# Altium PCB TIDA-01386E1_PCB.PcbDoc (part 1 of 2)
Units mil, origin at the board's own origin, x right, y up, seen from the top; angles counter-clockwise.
Board outline 3000 x 700 mil, 4 copper layers (Top Layer, Signal Layer 1, Signal Layer 2, Bottom Layer), stack 90.316 mil thick; 67 components, 41 nets, 217 pads, 102 vias.
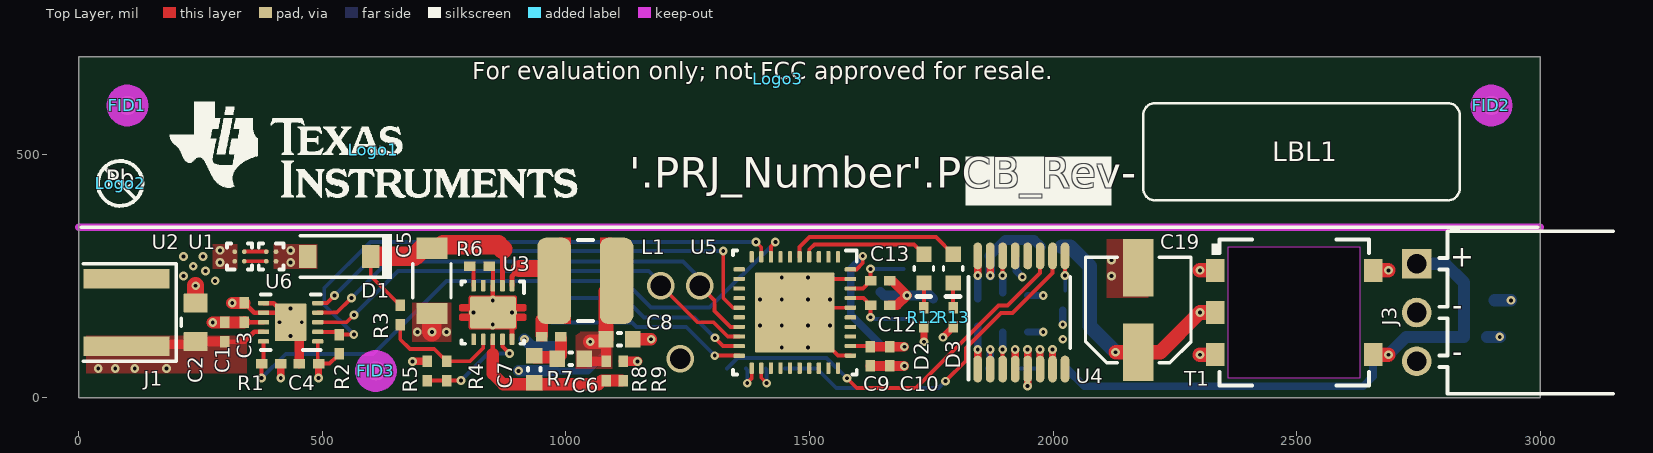
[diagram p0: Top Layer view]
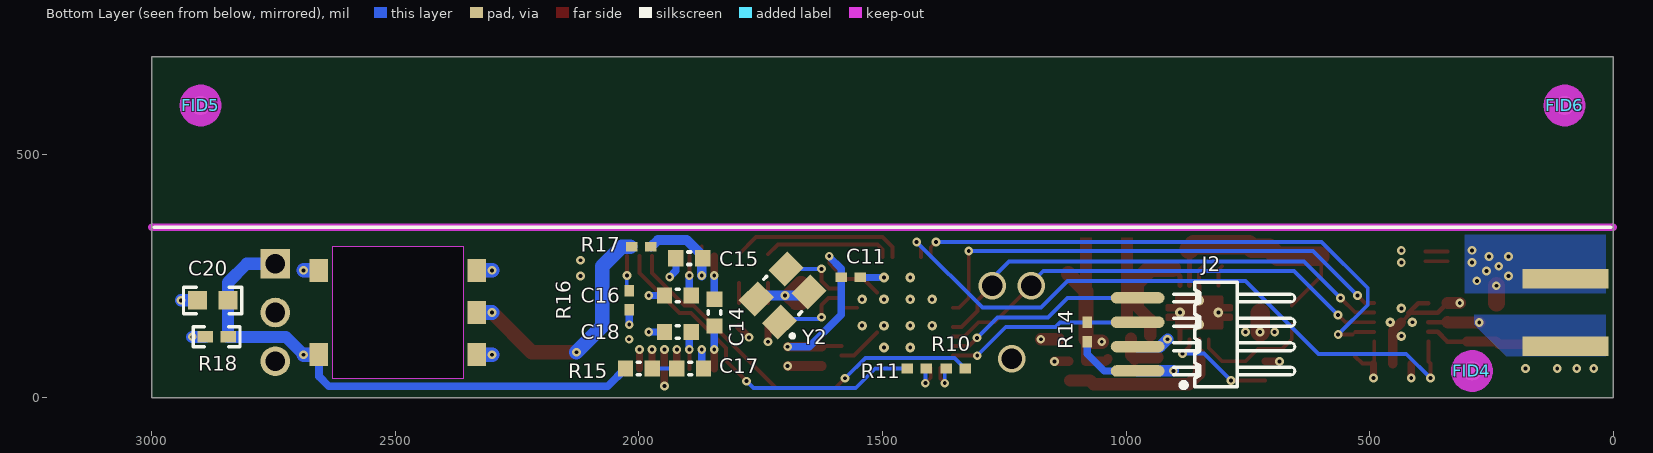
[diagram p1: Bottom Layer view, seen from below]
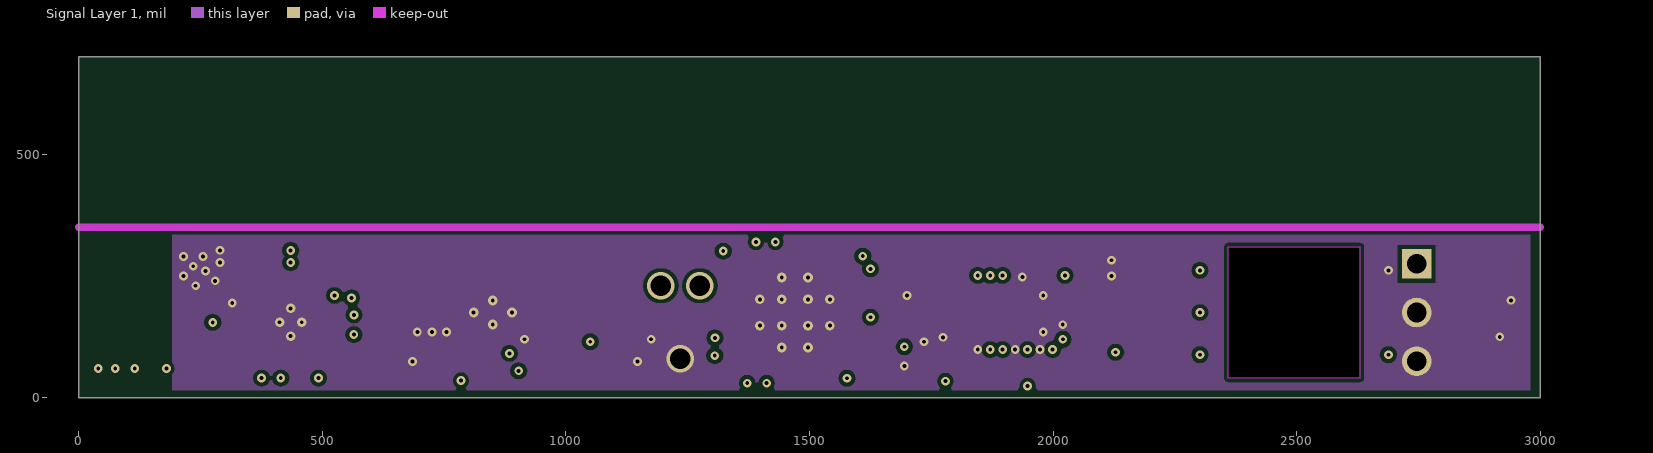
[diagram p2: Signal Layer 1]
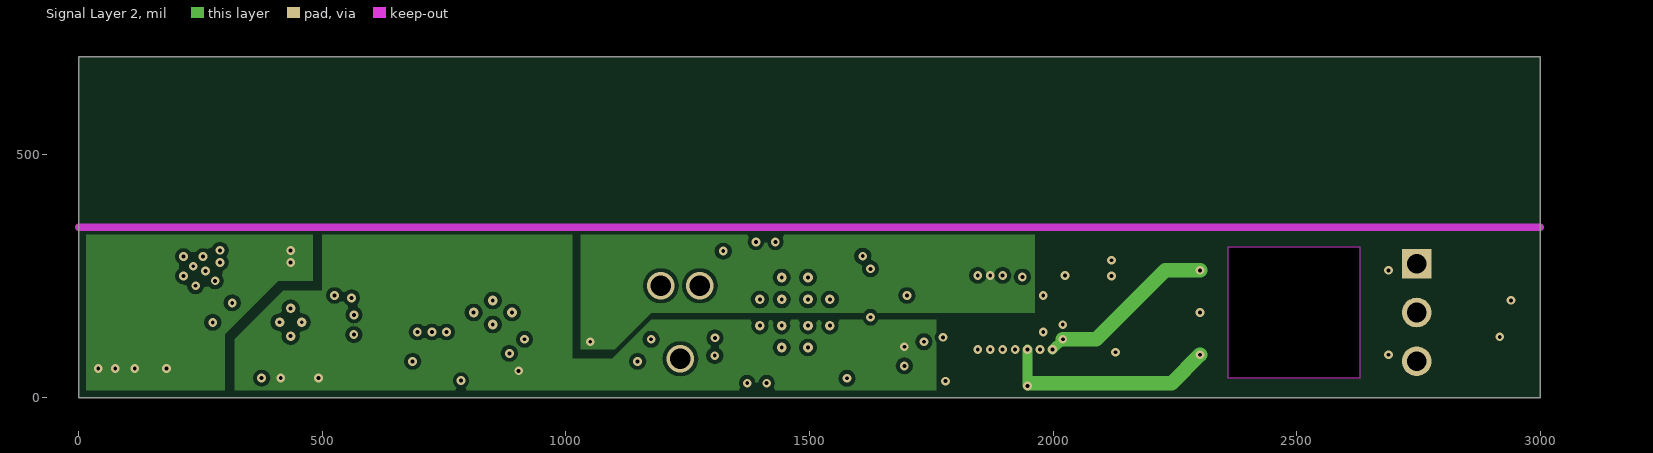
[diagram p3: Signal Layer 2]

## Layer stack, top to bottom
Top Solder: solder mask 0.4, Solder Resist, Dk 3.5
Top Layer: signal copper 1.457
Dielectric1: prepreg 20.079, FR-4, Dk 4.8
Signal Layer 1: signal copper 1.378
Dielectric 2: core 44.488, FR-4, Dk 4.8
Signal Layer 2: signal copper 1.378
Dielectric 3: prepreg 20.079, FR-4, Dk 4.8
Bottom Layer: signal copper 1.457
Bottom Solder: solder mask 0.4, Solder Resist, Dk 3.5

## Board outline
0,0 0,700 3000,700 3000,0
cut-out: 2630,40 2360,40 2360,310 2630,310

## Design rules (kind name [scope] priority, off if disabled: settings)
AcuteAngle [All] p1: minimum=4.50000000000000E+0001 checktracksonly=FALSE
AssemblyTestPointUsage [All] p1: valid=2
BoardOutlineClearance BoardOutlineClearance_MountingHoles [OnCopper and InComponentClass('Mounting Holes')] p1: gap=40
BoardOutlineClearance BoardOutlineClearance_Poly [OnCopper and IsPoly] p2: gap=20 except(15: Track-OutlineEdge Poly-OutlineEdge; 25: Text-OutlineEdge Text-CutoutEdge Text-CavityEdge Text-SplitBarrior Text-SplitContinuation)
BoardOutlineClearance [OnCopper and Not InComponentClass('Logo') and not InComponentClass('FiducialMark') and not InRegion(1000,500,4000,800) and not InPoly and not InComponent('J1')] p3: gap=75 except(7.87: Track-CutoutEdge SMDPad-CutoutEdge Fill-CutoutEdge Poly-CutoutEdge; 15: Track-OutlineEdge SMDPad-OutlineEdge Via-OutlineEdge Poly-OutlineEdge; 40: Arc-OutlineEdge Arc-CutoutEdge THPad-OutlineEdge THPad-CutoutEdge Via-CutoutEdge Fill-OutlineEdge Text-OutlineEdge Text-CutoutEdge)
Clearance Clearance_Keepouts [((IsTrack Or IsArc) And Not InPoly) And IsFree and IsKeepOut vs ((IsTrack Or IsArc) And Not InPoly) And IsFree and IsKeepOut] p1: gap=0
Clearance Clearance_Poly [InPolygon] p2: gap=25 except(8: Track-Poly SMDPad-Poly THPad-Poly Via-Poly Poly-Poly Poly-Region)
Clearance [All] p3: gap=7.87 except(6: Track-Track Track-SMDPad Track-THPad Track-Via; 7.5: Via-Via)
ComponentClearance ComponentClearance_MountingHoles_FiducialMarks [InComponentClass('Mounting Holes') vs InComponentClass('FiducialMark')] p1: gap=50 collisioncheckmode=3 verticalgap=10 showdistances=FALSE
ComponentClearance ComponentClearance_Shunt [InComponentClass('Header') vs InComponentClass('Shunt')] p2: gap=0 collisioncheckmode=3 verticalgap=0 showdistances=FALSE
ComponentClearance ComponentClearance_Logo [InComponentClass('Logo')] p3: gap=20 collisioncheckmode=3 verticalgap=10 showdistances=FALSE
ComponentClearance ComponentClearance_ScrewToNut [(HasFootprint('NY PMS 440 0025 PH')) vs (HasFootprint('Keystone_1902C'))] p4: gap=5 collisioncheckmode=3 verticalgap=10 showdistances=FALSE
ComponentClearance ComponentClearance_MountingHoles [InComponentClass('Mounting Holes')] p5: gap=250 collisioncheckmode=3 verticalgap=100000 showdistances=FALSE
ComponentClearance ComponentClearance_SmallPassives [HasFootprint('0201*') or HasFootprint('0402*') or HasFootprint('0508') or HasFootprint('0603*') or HasFootprint('0612') or HasFootprint('0805*') or HasFootprint('0815*') or HasFootprint('0830*') or HasFootprint('1206*') or HasFootprint('1210*') or HasFootprint('1808*') or HasFootprint('1812*') or HasFootprint('1825*') or HasFootprint('2010*') or HasFootprint('2220*') or HasFootprint('2225*') or HasFootprint('2512*') or HasFootprint('2728*') or HasFootprint('3518*') vs HasFootprint('0201*') or HasFootprint('0402*') or HasFootprint('0508') or HasFootprint('0603*') or HasFootprint('0612') or HasFootprint('0805*') or HasFootprint('0815*') or HasFootprint('0830*') or HasFootprint('1206*') or HasFootprint('1210*') or HasFootprint('1808*') or HasFootprint('1812*') or HasFootprint('1825*') or HasFootprint('2010*') or HasFootprint('2220*') or HasFootprint('2225*') or HasFootprint('2512*') or HasFootprint('2728*') or HasFootprint('3518*')] p6: gap=10 collisioncheckmode=3 verticalgap=10 showdistances=FALSE
ComponentClearance ComponentClearance_THtoSMT [IsThruComponent vs IsSMTComponent] p7: gap=40 collisioncheckmode=3 verticalgap=30 showdistances=FALSE
ComponentClearance ComponentClearance_THtoTH [IsThruComponent vs IsThruComponent] p8: gap=30 collisioncheckmode=3 verticalgap=30 showdistances=FALSE
ComponentClearance [All] p9: gap=20 collisioncheckmode=3 verticalgap=10 showdistances=FALSE
DiffPairsRouting [All] p1: maxlimit=100 minlimit=10 mostfreqgap=10 toplayer_minwidth=15 toplayer_maxwidth=15 toplayer_prefwidth=15 midlayer1_minwidth=15 midlayer1_maxwidth=15 midlayer1_prefwidth=15 midlayer2_minwidth=15 midlayer2_maxwidth=15 midlayer2_prefwidth=15 bottomlayer_minwidth=15 bottomlayer_maxwidth=15 bottomlayer_prefwidth=15 maxuncoupledlength=1000
FabricationTestPointUsage TestPointUsage [All] p1: valid=2 allowmultiple=FALSE
FabricationTestpoint Testpoint [All] p1: side=3 testpointundercomponent=TRUE minsize=40 maxsize=100 preferedsize=60 minholesize=0 maxholesize=40 preferedholesize=32 testpointgrid=1 allowsidetop=TRUE allowsidebottom=TRUE usegrid=TRUE gridtolerance=0.01
FanoutControl Fanout_LCC [IsLCC] p1: bgadir=Out bgaviamode=Centered fanoutstyle=Auto fanoutdirection=Alternating viagrid=1 // Fanout_LCC (Default Rule)
FanoutControl Fanout_BGA [IsBGA] p2: bgadir=Out bgaviamode=Centered fanoutstyle=Auto fanoutdirection=Alternating viagrid=1 // Fanout_BGA (Default Rule)
FanoutControl Fanout_Default [All] p4: bgadir=Out bgaviamode=Centered fanoutstyle=Auto fanoutdirection=Alternating viagrid=1 // Fanout_Default (Default Rule)
FanoutControl Fanout_Small [(CompPinCount < 5)] p5: bgadir=Out bgaviamode=Centered fanoutstyle=Auto fanoutdirection=OutThenIn viagrid=1 // Fanout_Small (Default Rule)
HoleSize [All] p1: absolutevalues=TRUE maxlimit=251 minlimit=7.87 maxpercent=80.000 minpercent=20.000
MinimumAnnularRing MinimumAnnularRing_ThermalPadVias [IsVia and InAnyComponent] p1: minimumring=5.91
MinimumAnnularRing [All] p2: minimumring=5
MinimumSolderMaskSliver MinimumSolderMaskSliver_Logo [InComponentClass('Logo') vs InComponentClass('Logo')] p1: minsoldermaskwidth=0.7
MinimumSolderMaskSliver [All] p2: minsoldermaskwidth=3.94
PlaneConnect [All] p1: planeconnectstyle=Relief reliefexpansion=10 reliefentries=4 reliefconductorwidth=10 reliefairgap=10
PolygonConnect [All] p1: connectstyle=Direct reliefconductorwidth=10 reliefentries=4 polygonreliefangle="90 Angle" airgapwidth=10
RoutingVias ThermalPadVias [IsVia and InAnyComponent] p1: holewidth=7.87 width=19.68 viastyle="Through Hole" minholewidth=7.87 minwidth=19.68 maxholewidth=12.99 maxwidth=23.62
RoutingVias [All] p2: holewidth=16 width=34 viastyle="Through Hole" minholewidth=7.87 minwidth=18 maxholewidth=42 maxwidth=65
SilkToBoardRegionClearance [Not ((IsComment or IsDesignator) And (Hide <> 'False')) and not InRegion(1000,500,4000,800)] p1:
SilkToSilkClearance SilkToSilkClearance_Pb-FreeLogo [(HasFootprint('Pb-Free_Overlay_Medium') OR HasFootprint('Pb-Free_Overlay_Small')) vs (HasFootprint('Pb-Free_Overlay_Medium') OR HasFootprint('Pb-Free_Overlay_Small'))] p1: silktosilkclearance=0
SilkToSilkClearance [All] p2: silktosilkclearance=4
SilkToSolderMaskClearance SilkToComponentPadClearance [IsPad and InAnycomponent] p1: minsilkscreentomaskgap=5 clearancetoexposedcopper=TRUE
SilkToSolderMaskClearance "Silk to Solder Mask Opening" [All] p2: minsilkscreentomaskgap=4 clearancetoexposedcopper=FALSE
SolderMaskExpansion [All] p1: expansion=1.97
Width [All] p1: maxlimit=100 minlimit=6 preferedwidth=10 checkconnectedcopper=TRUE
15 further rules are at their usual default settings.

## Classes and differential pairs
component class Label: LBL1
component class AssemblyNote: ZZ1 ZZ2 ZZ3 ZZ4
component class FiducialMark: FID1 FID2 FID3 FID4 FID5 FID6
component class TIDA-01386E1_EVM_Hardware: FID1 FID2 FID3 FID4 FID5 FID6 LBL1 Logo1 Logo2 Logo3 ZZ1 ZZ2 ZZ3 ZZ4
component class Logo: Logo1
component class TIDA-01386E1_BlankSheet: C1 C2 C3 C4 C5 C6 C7 C8 C9 C10 C11 C12 C13 C14 C15 C16 C17 C18 C19 C20 C30 C32 C34 C48 C49 D1 D2 D3 J1 J2 J3 L1 R1 R2 R3 R4 R5 R6 R7 R8 R9 R10 R11 R12 R13 R14 R15 R16 R17 R18 T1 U1 U2 U3 U4 U5 U6 Y2

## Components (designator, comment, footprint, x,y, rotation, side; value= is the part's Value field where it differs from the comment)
C1 "885012005062" 0402L 300,135 r90 top
C2 "CGA4J3X7S2A105K125AB" 0805_HV1 240,155 r90 top
C3 "885012005062" 0402L 340,175 r90 top
C4 "885012105012" 0402L 472.5,70 r180 top
C5 "C3216X7S2A225K160AB" 1206_180 725,240 r270 top
C6 "885012206083" 0603L 1010,80 r180 top
C7 "885012006057" 0603L 935,58.5 r270 top
C8 "C1608X5R1A226M080AC" 0603L 1110,120 r0 top
C9 "GRM155R71E104KE14D" 0402L 1625,85 r270 top
C10 "885012105012" 0402L 1665,85 r270 top
C11 "GRM155R71E104KE14D" 0402L 1565,247.5 r180 bottom
C12 "885012005009" 0402L 1645,190 r0 top
C13 "885012005009" 0402L 1645,240 r0 top
C14 "C1608X7R1H104K080AA" 0603L 1845,175 r270 bottom
C15 "C1608X7R1H104K080AA" 0603L 1896.61,286.14 r0 bottom
C16 "C1608X7R1H104K080AA" 0603L 1920,210 r0 bottom
C17 "GRM1885C2A750JA01D" 0603L 1895,60 r0 bottom
C18 "06031C103JAT2A" 0603L 1920,135 r0 bottom
C19 "EMVA350ADA220ME55G" CAPSMT_62_E55 2175,180 r90 top
C20 "C1608C0G2A101F080AA" 0603 2875,200 r0 bottom
D1 "RF071M2S" SOD-123 535,290 r180 top
D2 "LY L29K-J1K2-26-Z" "LY L29K_Yellow" 1735,265 r270 top
D3 "LG L29K-G2J1-24-Z" "LG L29K_GREEN" 1795,265 r270 top
FID1 "Fiducial" Fiducial10-20 100,600 r0 top
FID2 "Fiducial" Fiducial10-20 2900,600 r0 top
FID3 "Fiducial" Fiducial10-20 610,55 r0 top
FID4 "Fiducial" Fiducial10-20 290,55 r180 bottom
FID5 "Fiducial" Fiducial10-20 2900,600 r180 bottom
FID6 "Fiducial" Fiducial10-20 100,600 r180 bottom
J1 "09 0431 212 04" Binder_713_763_Edge_ENGR-ONLY 98,175 r90 top
J2 "850-10-004-40-001000" Mill-max_850-10-004-40-001000 815,130 r90 bottom
J3 "PPPC031LGBN-RC" Sullins_PPxC031LGBN-RC 3150,175 r270 top
L1 "744773147" WE-PD2-S 1040,240 r0 top
LBL1 "Size: 0.65\" x 0.20 \"" Label_650x200 2510,505 r0 top
Logo1 "Texas Instruments" TI_Stacked_Overlay_Small 605,509 r0 top
Logo2 "Pb-Free Symbol" Pb-Free_Overlay_Small 85,440 r0 top
Logo3 "FCC disclaimer" FCC_disclaimer 1435,655 r0 top
R1 "CRCW040210K0JNED" 0402L 395,70 r0 top
R2 "CRCW040210K0JNED" 0402L 535,110 r270 top
R3 "CRCW04021M00JNED" 0402L 660,170 r90 top
R4 "CRCW040288K7FKED" 0402L 755,55 r90 top
R5 "CRCW040237K4FKED" 0402L 715,55 r270 top
R6 "CRCW040282K5FKED" 0402L 822.5,270 r180 top
R7 "CRCW0402357KFKED" 0402L 970,125 r0 top
R8 "CRCW0402169KFKED" 0402L 1082.5,55 r90 top
R9 "CRCW040230K1FKED" 0402L 1117.5,55 r270 top
R10 "MCR01MZPJ470" 0402L 1350,60 r0 bottom
R11 "MCR01MZPJ470" 0402L 1430,60 r180 bottom
R12 "CRCW0402820RJNED" 0402L 1735,165 r270 top
R13 "CRCW0402820RJNED" 0402L 1795,165 r270 top
R14 "CRCW040247K0JNED" 0402L 1080,135 r270 bottom
R15 "CRCW0603100RFKEA" 0603L 2000,60 r180 bottom
R16 "CRCW040210K0JNED" 0402L 2020,200 r90 bottom
R17 "CRCW0402100RFKED" 0402L 1995,310 r180 bottom
R18 "CRCW04022K70JNED" 0402 2867,125 r180 bottom
T1 "B78416A2232A003" TDK_B78416A2232A003 2495,175 r0 top
U1 "TVS3300YZFR" YZF0004-C01 395,290 r270 top
U2 "TVS3300YZFR" YZF0004-C01 330,290 r90 top
U3 "LM5166DRCR" DRC0010J 850,175 r270 top
U4 "PGA460TPWRQ1" PW0016A_N 1935,175 r90 top
U5 "MSP430FR5959IRHAR" RHA0040B 1470,175 r270 top
U6 "TIOL111" TIOL111 435,155 r180 top
Y2 "ABM8-14.7456MHZ-10-1-U-T" ABRACON_ABM8G 1705,210 r45 bottom
ZZ1 "This Assembly Note is for PCB labels only" AssemblyNoteLabel 95,1618 r0 top
ZZ2 "These assemblies are ESD sensitive, ESD precautions shall be observed." AssemblyNote 95,1509.11 r0 top
ZZ3 "These assemblies must be clean and free from flux and all contaminants. Use of no clean flux is not acceptable." AssemblyNote 95,1420.56 r0 top
ZZ4 "These assemblies must comply with workmanship standards IPC-A-610 Class 2, unless otherwise specified." AssemblyNote 95,1332 r0 top

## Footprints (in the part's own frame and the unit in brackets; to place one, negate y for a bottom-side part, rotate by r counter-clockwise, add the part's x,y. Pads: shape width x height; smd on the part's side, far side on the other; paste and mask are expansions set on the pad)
0402 [mm] "0402 from SM-752 data"
  rect 0.8x0.6 smd: 1(-0.6,0) 2(0.6,0)
  silkscreen extent -1.22,-0.52 1.22,0.52, body extent -0.55,-0.3 0.55,0.3, height 0.6
0402L [mm] "0402 from SM-752 data"
  rect 0.6x0.5 smd: 1(-0.5,0) 2(0.5,0)
  body extent -0.55,-0.3 0.55,0.3, height 0.6
0603 [mm] "0603 from SM-752 data"
  rect 1x0.95 smd: 1(-0.8,0) 2(0.8,0)
  silkscreen extent -1.52,-0.69 1.52,0.69, body extent -0.87,-0.47 0.87,0.47, height 1
0603L [mm] "0603 from SM-752 data"
  rect 0.8x0.85 smd: 1(-0.7,0) 2(0.7,0)
  silkscreen extent -0.07,-0.32 0.07,0.32, body extent -0.87,-0.47 0.87,0.47, height 1
0805_HV1 [mm] "Custom footprint based on analyzing multiple manufacturer recommendations"
  rrect10% 1x1.25 smd: 1(-1,0) 2(1,0)
  silkscreen extent -0.2,0.75 0.2,0.75, body extent -1.1,-0.72 1.1,0.73, height 1.45
1206_180 [mm] "1206_180"
  rect 1.1x1.6 smd: 1(-1.7,0) 2(1.7,0)
  silkscreen extent -0.9,-1 0.9,1, body extent -1.75,-0.95 1.75,0.95, height 1.8
ABRACON_ABM8G [mm] "ABRACON"
  rect 1.2x1.4 smd: 1(-0.85,1.1) 2(-0.85,-1.1) 3(0.85,-1.1) 4(0.85,1.1)
  silkscreen extent -1.92,-0.1 1.3,1.21, body extent -1.3,-1.65 1.3,1.65, height 1.01
AssemblyNote [mil] "Assembly Note"
AssemblyNoteLabel [mil] "Assembly Note for PCB Labels"
Binder_713_763_Edge_ENGR-ONLY [mm] "Binder-Connector-Edge Mount, Non IPC Compiant"
  rect 1x4.5 smd: 1(-1.756,0) 2(1.756,0)
  rect 1x4.5 smd far side: 3(1.756,0) 4(-1.756,0)
  silkscreen extent -2.55,-2.6 2.55,2.25, body extent -8.46,-1.4 8.46,16.8, height 7.21
CAPSMT_62_E55 [mm] "5 x 5.2mm:  Chemi-Con E55"
  rect 3x1.6 smd: 1(-2.2,0) 2(2.2,0)
  silkscreen extent -2.75,-2.75 2.75,2.75, body extent -2.75,-2.75 2.75,2.75, height 5.5
DRC0010J [mm] "SON, 10-Leads, Body 3x3mm, Pitch 0.5mm, Thermal Pad 2.4x1.65mm, TI Recommended"
  rrect40% 0.6x0.25 smd: 1(-1.4,1) 2(-1.4,0.5) 3(-1.4,0) 4(-1.4,-0.5) 5(-1.4,-1) 6(1.4,-1) 7(1.4,-0.5) 8(1.4,0) 9(1.4,0.5) 10(1.4,1)
  rrect40% 0.25x0.34 on Top Paste: 11(-0.25,1.53) 11(-0.25,-1.53) 11(0.25,1.53) 11(0.25,-1.53)
  rrect9% 1.5x1.06 on Top Paste: 11(0,0.63) 11(0,-0.63)
  rrect12% 1.65x2.4 smd paste-1 mask-2: 11(0,0)
  Top Layer region: -0.775,-1.25 -0.425,-1.25 -0.425,-1.65 -0.417,-1.688 -0.396,-1.721 -0.363,-1.742 -0.325,-1.75 -0.325,-1.75 -0.325,-1.75 -0.175,-1.75 -0.175,-1.75 -0.137,-1.742 -0.104,-1.721 -0.083,-1.688 -0.075,-1.65 -0.075,-1.65 -0.075,-1.25 0.075,-1.25 0.075,-1.65 0.083,-1.688 0.104,-1.721 0.137,-1.742 0.175,-1.75 0.175,-1.75 0.175,-1.75 0.325,-1.75 0.325,-1.75 0.363,-1.742 0.396,-1.721 0.417,-1.688 0.425,-1.65 0.425,-1.65 0.425,-1.25 0.775,-1.25 0.813,-1.242 0.846,-1.221 0.867,-1.188 0.875,-1.15 0.875,-1.15 0.875,1.15 0.867,1.188 0.846,1.221 0.813,1.242 0.775,1.25 0.775,1.25 0.425,1.25 0.425,1.65 0.417,1.688 0.396,1.721 0.363,1.742 0.325,1.75 0.325,1.75 0.175,1.75 0.137,1.742 0.104,1.721 0.083,1.688 0.075,1.65 0.075,1.65 0.075,1.25 -0.075,1.25 -0.075,1.65 -0.083,1.688 -0.104,1.721 -0.137,1.742 -0.175,1.75 -0.175,1.75 -0.325,1.75 -0.363,1.742 -0.396,1.721 -0.417,1.688 -0.425,1.65 -0.425,1.65 -0.425,1.25 -0.775,1.25 -0.813,1.242 -0.846,1.221 -0.867,1.188 -0.875,1.15 -0.875,1.15 -0.875,-1.15 -0.867,-1.188 -0.846,-1.221 -0.813,-1.242 -0.775,-1.25
  silkscreen extent -1.63,-1.63 1.63,1.63, body extent -1.5,-1.5 1.5,1.5, height 0.77
FCC_disclaimer [mil]
Fiducial10-20 [mm]
  round 1 smd mask+0.5: 1(0,0)
  Top Layer keep-out circle w1.178: c0,0 r0.5
Label_650x200 [mil] "Thermal Transfer Label"
  silkscreen extent -325,-100 325,100, body extent -325,-100 325,100, height 1
"LG L29K_GREEN" [mm] "OSRAM"
  rect 0.8x0.8 smd paste-0.4: 1(-0.75,0) 2(0.75,0)
  silkscreen extent -0.1,-0.5 1.45,0.5, body extent -0.9,-0.45 0.9,0.45, height 0.67
"LY L29K_Yellow" [mm] "OSRAM"
  rect 0.8x0.8 smd paste-0.4: 1(-0.75,0) 2(0.75,0)
  silkscreen extent -0.1,-0.5 1.45,0.5, body extent -0.9,-0.45 0.9,0.45, height 0.67
Mill-max_850-10-004-40-001000 [mm] "Mill-max"
  oval 0.6x2.8 smd: 1(-1.905,4.1) 2(-0.635,4.1) 3(0.635,4.1) 4(1.905,4.1)
  silkscreen extent -2.78,-4.1 2.72,2.21, body extent -2.73,-4.08 2.74,5.43, height 2.13
Pb-Free_Overlay_Small [mil]
  silkscreen extent -46,-46 46,46
PW0016A_N [mm] "TSOP, 16-Leads, Body 5x4.4mm, Pitch 0.65mm, IPC Medium Density"
  oval 1.4x0.45 smd: 1(-2.95,2.275) 2(-2.95,1.625) 3(-2.95,0.975) 4(-2.95,0.325) 5(-2.95,-0.325) 6(-2.95,-0.975) 7(-2.95,-1.625) 8(-2.95,-2.275) 9(2.95,-2.275) 10(2.95,-1.625) 11(2.95,-0.975) 12(2.95,-0.325) 13(2.95,0.325) 14(2.95,0.975) 15(2.95,1.625) 16(2.95,2.275)
  silkscreen extent -3.5,-2.55 1.85,2.75, body extent -3.21,-2.5 3.21,2.5, height 1
RHA0040B [mm] "QFN, 40-Leads, Body 6x6mm, Pitch 0.5mm, Thermal Pad 4.15 x 4.15mm, TI Recommended"
  rrect45% 0.6x0.22 smd mask+0.07: 1(-2.9,2.25) 2(-2.9,1.75) 3(-2.9,1.25) 4(-2.9,0.75) 5(-2.9,0.25) 6(-2.9,-0.25) 7(-2.9,-0.75) 8(-2.9,-1.25) 9(-2.9,-1.75) 10(-2.9,-2.25) 21(2.9,-2.25) 22(2.9,-1.75) 23(2.9,-1.25) 24(2.9,-0.75) 25(2.9,-0.25) 26(2.9,0.25) 27(2.9,0.75) 28(2.9,1.25) 29(2.9,1.75) 30(2.9,2.25)
  rrect45% 0.22x0.6 smd mask+0.07: 11(-2.25,-2.9) 12(-1.75,-2.9) 13(-1.25,-2.9) 14(-0.75,-2.9) 15(-0.25,-2.9) 16(0.25,-2.9) 17(0.75,-2.9) 18(1.25,-2.9) 19(1.75,-2.9) 20(2.25,-2.9) 31(2.25,2.9) 32(1.75,2.9) 33(1.25,2.9) 34(0.75,2.9) 35(0.25,2.9) 36(-0.25,2.9) 37(-0.75,2.9) 38(-1.25,2.9) 39(-1.75,2.9) 40(-2.25,2.9)
  rrect9% 1.17x1.17 on Top Paste: 41(-1.37,1.37) 41(-1.37,0) 41(-1.37,-1.37) 41(0,-1.37) 41(0,1.37) 41(0,0) 41(1.37,1.37) 41(1.37,0) 41(1.37,-1.37)
  rrect2% 4.15x4.15 smd paste-2.1: 41(0,0)
  silkscreen extent -3.22,-3.22 3.22,3.22, body extent -3,-3 3,3, height 1
SOD-123 [mm] "On Semi recommended land pattern"
  rect 0.915x1.22 smd: 1(-1.637,0) 2(1.637,0)
  silkscreen extent -2.74,-1.17 2.03,1.17, body extent -1.93,-0.9 1.93,0.9, height 1.35
Sullins_PPxC031LGBN-RC [mm] "Receptacle, 2.54 mm, 3x1, R/A, TH"
  rect 1.55x1.55 hole 1.02: 1(-2.54,-10.25)
  round 1.55 hole 1.02: 2(0,-10.25) 3(2.54,-10.25)
  silkscreen extent -4.5,-9.08 4.24,0, body extent -4.24,-10.55 4.24,0, height 2.75
TDK_B78416A2232A003 [mm] "SMT, 5-Leads, Body 8.8x7.6mm"
  rect 0.971x1.2 smd: 1(-4.115,2.2) 2(-4.115,0) 3(-4.115,-2.2) 4(4.115,-2.2) 6(4.115,2.2)
  silkscreen extent -4.3,-3.8 3.9,3.8, body extent -4.5,-3.8 4.5,3.8, height 7.1
TI_Stacked_Overlay_Small [mil]
  silkscreen extent -418,-98 418,98
TIOL111 [mm] "SON, 10-Leads, Body 2.5x3mm, Pitch 0.5mm, Thermal Pad 1.95x1.65mm"
  rrect40% 0.575x0.24 smd: 1(-1.412,1) 2(-1.412,0.5) 3(-1.412,0) 4(-1.412,-0.5) 5(-1.412,-1) 6(1.412,-1) 7(1.412,-0.5) 8(1.412,0) 9(1.412,0.5) 10(1.412,1)
  rrect6% 1.65x1.95 smd paste-2: 11(0,0)
  silkscreen extent -1.55,-1.45 1.55,1.45, body extent -1.55,-1.3 1.55,1.3, height 1.02
WE-PD2-S [mm] "WURTH"
  rrect50% 1.75x4.5 smd: 1(-1.625,0) 2(1.625,0)
  Top Layer region: 1.375,2.25 0.75,2.25 0.75,-2.25 1.375,-2.25
  Top Layer region: -1.375,-2.25 -0.75,-2.25 -0.75,2.25 -1.375,2.25
  silkscreen extent -0.4,-2.1 0.4,2.12, body extent -2.25,-2 2.25,2, height 3.18
YZF0004-C01 [mm] "BGA, 4-Balls, Body 1.062x1.116mm, Pitch 0.5mm"
  round 0.245 smd paste-0.125: A1(-0.25,0.25) A2(0.25,0.25) B1(-0.25,-0.25) B2(0.25,-0.25)
  silkscreen extent -0.68,-0.65 0.67,0.65, body extent -0.57,-0.55 0.57,0.55, height 0.63

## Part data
C1 C3: "CAP, CERM, 150 pF, 50 V, +/- 5%, C0G/NP0, 0402"
C2: "CAP, CERM, 1 µF, 100 V, +/- 10%, X7S, AEC-Q200 Grade 1, 0805"
C4 C10: "CAP, CERM, 1 µF, 10 V, +/- 20%, X5R, 0402"
C5: "CAP, CERM, 2.2 µF, 100 V, +/- 10%, X7S, 1206"
C6: "CAP, CERM, 1000 pF, 50 V, +/- 10%, X7R, 0603"
C7: "CAP, CERM, 100 pF, 50 V, +/- 5%, C0G/NP0, 0603"
C8: "CAP, CERM, 22 µF, 10 V, +/- 20%, X5R, 0603"
C9 C11: "CAP, CERM, 0.1 µF, 25 V, +/- 10%, X7R, 0402"
C12 C13: "CAP, CERM, 22 pF, 10 V, +/- 5%, C0G/NP0, 0402"
C14 C15 C16: "CAP, CERM, 0.1 µF, 50 V, +/- 10%, X7R, 0603"
C17: "CAP, CERM, 75 pF, 100 V, +/- 5%, C0G/NP0, 0603"
C18: "CAP, CERM, 0.01 µF, 100 V, +/- 5%, X7R, 0603"
C19: "CAP, AL, 22 µF, 35 V, +/- 20%, SMD"
C20: "CAP, CERM, 100 pF, 100 V, +/- 1%, C0G/NP0, 0603"
D1: "Diode, Ultrafast, 200 V, 1 A, SOD-123"
D2: "LED, Yellow, SMD"
D3: "LED, Green, SMD"
FID1 FID2 FID3 FID4 FID5 FID6: "Fiducial mark.  There is nothing to buy or mount."
J1: "M12 Socket, 4Pos, TH"
J2: "Header, 50mil, 4x1, Gold, R/A, SMT"
J3: "Receptacle, 2.54 mm, 3x1, Gold, R/A, TH"
L1: "Inductor, Shielded Drum Core, Ferrite, 47 µH, 0.68 A, 0.844 ohm, SMD"
LBL1: library part THT-14-423-10, "Thermal Transfer Printable Labels, 0.650\" W x 0.200\" H - 10,000 per roll"
Logo1: library part TI_Logo, "Texas Instrument Corporate Signature"
Logo2: library part Pb-Free
Logo3: library part FCC_disclaimer, "FCC_disclaimer"
R1 R2 R16: "RES, 10 k, 5%, 0.063 W, 0402"
R3: "RES, 1.0 M, 5%, 0.063 W, 0402"
R4: "RES, 88.7 k, 1%, 0.063 W, 0402"
R5: "RES, 37.4 k, 1%, 0.063 W, 0402"
R6: "RES, 82.5 k, 1%, 0.063 W, AEC-Q200 Grade 0, 0402"
R7: "RES, 357 k, 1%, 0.063 W, 0402"
R8: "RES, 169 k, 1%, 0.063 W, 0402"
R9: "RES, 30.1 k, 1%, 0.063 W, 0402"
R10 R11: "RES, 47, 5%, 0.063 W, 0402"
R12 R13: "RES, 820, 5%, 0.063 W, 0402"
R14: "RES, 47k ohm, 5%, 0.063W, 0402"
R15: "RES, 100, 1%, 0.1 W, 0603"
R17: "RES, 100, 1%, 0.063 W, 0402"
R18: "RES, 2.7 k, 5%, 0.063 W, 0402"
T1: "Transformer, 3 mH, SMT"
U1 U2: "33V Precision Surge Protection Clamp, YZF0004-C01 (DSBGA-4)"
U3: "3.0-V to 65-V Input, 500-mA Synchronous Buck Converter with Ultra-Low IQ, DRC0010J (VSON-10)"
U4: "PGA460TPWRQ1, PW0016A"
U5: "MSP430FR5959 16 MHz Ultra-Low-Power Microcontroller featuring 64 KB FRAM, 2 KB SRAM, 33 IO, RHA0040B (VQFN-40)"
U6: "IO-Link Device Transceiver with Integrated Surge Protection, TIOL111 (WSON-10)"
Y2: library part CMP-0076763-1, "Crystal, 14.7456 MHz, 10 pF, SMD"
ZZ1: library part AssemblyNoteLabel
ZZ2 ZZ3 ZZ4: library part AssemblyNote

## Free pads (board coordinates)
  rect 38.23x47.24 smd far side: 3(2333.01,88.39) 3(2333.01,175) 3(2333.01,261.61) 3(2656.99,88.39) 3(2656.99,261.61)

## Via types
v1: diameter 18, hole 8, Top Layer to Bottom Layer, tented both sides, 79 vias
v2: diameter 19.68, hole 7.87, Top Layer to Bottom Layer, 16 vias
v3: diameter 19.68, hole 7.87, Top Layer to Bottom Layer, tented bottom, 4 vias
v4: diameter 56, hole 42, Top Layer to Bottom Layer, 3 vias

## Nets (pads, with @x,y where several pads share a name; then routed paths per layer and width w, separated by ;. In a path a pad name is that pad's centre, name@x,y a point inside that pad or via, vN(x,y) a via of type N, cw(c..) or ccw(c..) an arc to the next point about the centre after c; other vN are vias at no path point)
3V3: C4.1 C9.1 C10.1 C11.1 J2.1 R1.2 R2.2 R14.2 U5.32 U5.40 U6.1 | length 794.7
  Top Layer w8: U6.1@490.61,115.63 490.61,71.57 C4.1@492.18,70 515,70 530,85 R2.2@530,90 ; U5.32@1584.17,106.1 1623.58,106.1 C9.1@1625,104.68 ; U5.40@1584.17,263.58 1596.58,263.58 1609.32,276.32 v1(1609.32,290.68)
  Top Layer w15: v1(414.69,40.32) R1.2@414.69,70 ; v1(492.18,40.32) C4.1@492.18,70
  Top Layer w20: C9.1@1625,104.68 C10.1@1665,104.69 v1(1694.69,104.69)
  Bottom Layer w15: J2.1@976.42,55 1045,55 1080,90 R14.2@1080,115.31 ; v1@1610,290 1584.68,264.68 C11.1@1584.68,247.5 1584.68,170.32 1650.31,104.69 v1(1694.69,104.69)
  Bottom Layer w23.62: v1@903,55 J2.1@976.42,55
  other v1: 903,55.2
\FAULT: R2.1 U5.9 U6.2 | length 1149.7
  Top Layer w8: U6.2@490.61,135.32 R2.1@529.37,135.32 ; R2.1@535,129.68 v1(564.68,129.68) ; v1(1390,320) 1401.1,308.9 U5.9@1401.1,289.17
  Bottom Layer w8: v1(564.68,129.68) 504,190.37 504,225 599,320 v1(1390,320)
A1RX: U5.18 U6.3 | length 982.3
  Top Layer w8: U6.3@490.61,155 550,155 v1(565,170) ; v4(1195,230) 1270,155 1303,155 1332.21,125.79 U5.18@1355.83,125.79 ; v4@1200,217 v4@1200,230
  Bottom Layer w8: v1(565,170) 655,260 1170,260 v4@1200,230
A1TX: U5.17 U6.4 | length 992.4
  Top Layer w8: U6.4@490.61,174.68 529.68,174.68 v1(560,205) ; v4(1275,230) 1305,200 1305,178 1337.53,145.47 U5.17@1355.83,145.47
  Bottom Layer w8: v1(560,205) 635,280 1240,280 v4@1290,230
AVDD: C14.1 U4.16 | length 88.8
  Top Layer w15: v1(1845.43,251.14) U4.16@1845.43,291.14
  Bottom Layer w15: C14.1@1845,202.56 1845.43,202.99 v1(1845.43,251.14)
EN: U5.15 U6.5 | length 1013.7
  Top Layer w8: U6.5@490.61,194.37 509.37,194.37 v1(525,210) ; v1(1323,301) 1323,205 1343.16,184.84 U5.15@1355.83,184.84
  Bottom Layer w8: v1(525,210) 616,301 v1(1323,301)
INN: C18.1 U4.3 | length 76.5
  Top Layer w8: U4.3@1896.61,58.86 v1(1896.61,98.86)
  Bottom Layer w15: v1(1896.61,98.86) 1896.61,134.17 C18.1@1897.44,135
INP: C17.1 U4.2 | length 75.3
  Top Layer w8: U4.2@1871.02,58.86 v1(1871.02,98.86)
  Bottom Layer w15: C17.1@1867.44,60 C17.1@1871.02,63.58 ; C17.1@1871.02,68.58 v1(1871.02,98.86)
IOREG: C16.1 U4.14 | length 76.5
  Top Layer w8: v1(1896.61,251.14) U4.14@1896.61,291.14
  Bottom Layer w15: v1(1896.61,251.14) 1896.61,215.83 C16.1@1897.44,215
L+: C1.1 C2.1 D1.2 J1.1 U1.A1 U1.A2 U6.9 | length 301.9
  Top Layer w9.4: C1.1@300,115.32 340.32,115.32 360.32,135.32 U6.9@379.39,135.32
  Top Layer w20: J1.1@90,105.85 94.15,110 234.37,110 C2.1@240,115.63 240.31,115.32 C1.1@300,115.32
  other v1: 40,60 75,60 115,60 180,60 435,277.5 435,302.5
L-: C2.2 C3.2 C4.2 C5.2 C8.2 C9.2 C10.2 C11.2 C12.2 C13.2 C14.2 C15.2 C16.2 C18.2 C19.2 C20.2 J1.3 J2.2 J3.2 J3.3 pad.3@2656.99,261.61 R5.1 R6.1 R9.1 R12.2 R13.2 R16.1 R18.1 T1.6 U2.A1 U2.A2 U3.3 U3.10 U3.11@850,175 U4.1 U4.4 U4.6 U5.31 U5.36 U5.39 U5.41@1470,175 U6.6 U6.7 U6.11 Y2.2 Y2.4 | length 1723.7
  Top Layer w8: U6.11@415.32,174.68 U6.11@435,155 ; R6.1@842.18,270 850,262.18 U3.3@850,230.12 ; U3.11@850,175 v3(850,199.61) ; U5.41@1511,134 1558.58,86.42 U5.31@1584.17,86.42 ; U5.41@1511,216 1538.9,243.9 U5.39@1584.17,243.9 ; 1551.87,184.84 U5.36@1584.17,184.84
  Top Layer w9.4: U6.6@379.39,194.37 400.63,194.37 U6.11@420.32,174.68
  Top Layer w9.5: C3.2@340,194.69 360,174.68 U6.7@379.39,174.68 415.32,174.68 U6.11@420.32,174.68
  Top Layer w9.8: U3.11@850,175 865,175 889.37,150.63 U3.10@889.37,119.88 ; v3(850,199.61) U3.3@850,230.12
  Top Layer w15: v1(685.32,74.68) R5.1@715,74.68 ; v1(1735,115) R12.2@1735,145 ; v1(1774,124) 1774,124.31 R13.2@1795,145.31 ; U4.1@1845.43,58.86 v1(1845.43,98.86) ; U4.4@1922.2,58.86 v1(1922.2,98.86) ; U4.6@1973.39,58.86 v1(1973.39,98.86)
  Top Layer w20: U6.11@435,155 452.81,137.19 C4.2@452.81,70 ; R9.1@1117.5,74.68 v1(1147.19,74.69) ; C9.2@1625,65.31 C10.2@1665,65.31 v1(1694.69,65.32) ; C12.2@1664.69,190 1680,190 v1(1700,210) 1670,240 C13.2@1664.69,240
  Top Layer w25: v1(315,194.69) C3.2@340,194.69 ; C8.2@1137.56,120 v1(1175,120)
  Top Layer w30: T1.6@2656.89,261.61 v1(2688.39,261.61)
  Top Layer w35: C2.2@240,194.37 v1(240,230)
  Top Layer w40: v1(725,135) C5.2@725,173.07
  Bottom Layer w15: v2(1496.97,246.85) 1544.67,246.85 C11.2@1545.31,247.5 ; C14.2@1845,147.44 1845.43,147.01 v1(1845.43,98.86) ; C15.2@1924.17,286.14 1924.17,260.83 v1(1937,248) ; C18.2@1947.56,135 v1(1980,135) ; C16.2@1947.56,210 v1(1980,210) ; v1(2020,150) R16.1@2020,180.32
  Bottom Layer w20: Y2.2@1645.71,216.96 1652.67,210 v1(1700,210) 1747.33,210 Y2.4@1754.29,203.04
  Bottom Layer w23.62: v1(915,120) 930,105 J2.2@976.42,105
  Bottom Layer w25: R18.1@2890.62,125 v1(2917,125) ; C20.2@2906.5,200 v1(2940,200)
  Bottom Layer w30: pad.3@2656.89,261.61 v1(2688.39,261.61)
  other v1: 695,135 755,135 280,240 215,250 2120,250 260,260 235,270 290.16,277.66 2120,282.28 215,290 255,290 290.16,302.66
  other v2: 1443.03,103.15 1496.97,103.15 435,126.46 1398.15,148.03 1443.03,148.03 1496.97,148.03 1541.85,148.03 412.36,155 457.64,155 435,183.54 1398.15,201.97 1443.03,201.97 1496.97,201.97 1541.85,201.97 1443.03,246.85
  other v3: 850,150.39 810.63,175 889.37,175
  other v4: 1235,80
NetC1_2: C1.2 C3.1 J1.4 U6.8 | length 104.8
  Top Layer w8: C3.1@340,155.32 C3.1@340.32,155
  Top Layer w9.4: C3.1@340.32,155 U6.8@379.39,155
  Top Layer w25: v1(275,154.69) C1.2@300,154.69 339.37,154.69 C3.1@340,155.32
